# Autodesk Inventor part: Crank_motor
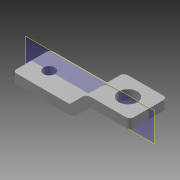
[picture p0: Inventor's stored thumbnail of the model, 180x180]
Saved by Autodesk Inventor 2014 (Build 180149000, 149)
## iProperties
Created: 2006-03
Part Number: Crank_motor
Document SubType Name: Modeling
Designer: debonom
Material: Stainless Steel, 440C
Mass: 46.8106 g
Surface Area: 35.1137 cm^2
Volume: 6.04008 cm^3
Density: 7.75 g/cm^3
Appearance: Steel
Author: debonom
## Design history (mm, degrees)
sketch "Sketch1"
  geometry: L1 (0, 0)-(-22.16, 0); L2 (0, 0)-(9, -9); L3 (9, -9)-(40.46, -9)
  constraints: 6 end point, 1 horizontal, 1 parallel
  dimensions: "d0" = 135 deg angle of L2 L1; "d1" = 62.62 horizontal distance of L3.end L1.end; "d2" = 22.16 distance of L1.start L1.end; "d3" = 9 distance between parallel lines of L3 L1
workplane "Work Plane1"
sketch "Sketch2"
  geometry: L1 (-10, 2.5)-(10, 2.5); L2 (10, 2.5)-(10, -2.5); L3 (10, -2.5)-(-10, -2.5); L4 (-10, -2.5)-(-10, 2.5); L5 (-10, 2.5)-(10, -2.5); 2 further points
  constraints: 10 end point, 2 parallel, 1 coincident, 1 horizontal, 1 midpoint, 1 perpendicular
  dimensions: "d4" = 20 distance of L1.start L1.end; "d5" = 5 distance of L3.end L1.start
sweep "Sweep1" sketch "Sketch2" dims "d6" = 0
fillet "Fillet1" dims "d7" = 7
fillet "Fillet2" dims "d8" = 2
sketch "Sketch3"
  geometry: L1 (-12.524, 10)-(75.144, 10) reference; L2 (0, 20)-(0, 0) reference; C1 r 3.05 at (9.5, 10); 1 further point
  constraints: 1 centre point, 1 point on line
  dimensions: "d9" = 9.5 distance from line of C1.centre L2; "d10" = 6.1 diameter of C1
extrude "Extrusion1" cut sketch "Sketch3" stored distance "d11" = 10; taper "d12" = 0 deg
sketch "Sketch4"
  geometry: L1 (-75.144, 10)-(12.524, 10) reference; L2 (0, 24)-(0, -4) reference; C1 r 5 at (-11, 10); 1 further point
  constraints: 1 centre point, 1 point on line
  dimensions: "d13" = 11 distance from line of C1.centre L2; "d14" = 10 diameter of C1
extrude "Extrusion2" cut sketch "Sketch4" stored distance "d15" = 10; taper "d16" = 0 deg
fillet "Fillet3" dims "d17" = 2
node "Mobile"
body "Solid1"
